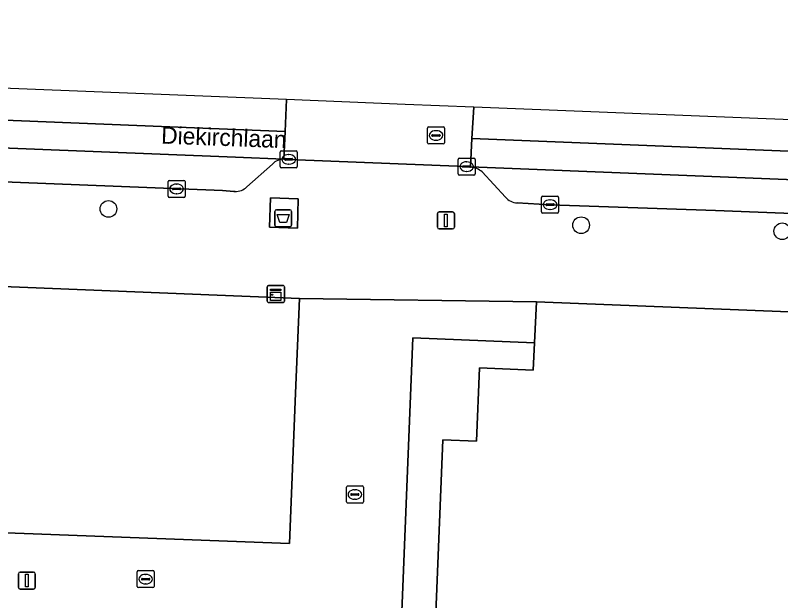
# Model space of a CAD drawing. Extents: x 160888 to 161385, y 386490 to 386908.
# Drawn here: x 161096.46 to 161141.39, y 386873.43 to 386907.8 of the extents above; entities that cross this region are included whole.
import ezdxf

# ---------------------------------------------------------------- set-up
doc = ezdxf.new("R2010")
doc.units = 0
for name, color, linetype in [('IMGEO_Afval_apart_plaats', 7, 'Continuous'), ('IMGEO_Boom', 7, 'Continuous'), ('IMGEO_Erf', 7, 'Continuous'), ('IMGEO_Kast', 7, 'Continuous'), ('IMGEO_Kolk', 7, 'Continuous'), ('IMGEO_Lichtmast', 7, 'Continuous'), ('IMGEO_Openbare_ruimte_label', 7, 'Continuous'), ('IMGEO_Pand', 7, 'Continuous'), ('IMGEO_Pand_overbouw', 7, 'Continuous'), ('IMGEO_Parkeervlak_gesloten', 7, 'Continuous'), ('IMGEO_Rijbaan_lokaal_gesloten', 7, 'Continuous'), ('IMGEO_Rioolput', 7, 'Continuous'), ('IMGEO_Voetpad_gesloten', 7, 'Continuous'), ('IMGEO_Voetpad_open', 7, 'Continuous')]:
    doc.layers.add(name, color=color, linetype=linetype)

msp = doc.modelspace()

# ---------------------------------------------------------------- linework, layer by layer
at = {"layer": 'IMGEO_Afval_apart_plaats'}
for p, q in [((161111.692, 386895.485), (161111.692, 386896.285)), ((161111.692, 386896.285), (161111.692, 386895.485)), ((161111.792, 386896.385), (161112.582, 386896.385)), ((161112.582, 386896.385), (161111.792, 386896.385)), ((161112.682, 386896.285), (161112.682, 386895.485)), ((161112.682, 386895.485), (161112.682, 386896.285)), ((161112.582, 386895.385), (161111.792, 386895.385)), ((161111.792, 386895.385), (161112.582, 386895.385))]:
    msp.add_line(p, q, dxfattribs=at)
msp.add_lwpolyline([(161111.835, 386896.099), (161112.539, 386896.099), (161112.39, 386895.629), (161111.984, 386895.629), (161111.835, 386896.099)], dxfattribs=at)
for centre, start, end in [((161111.792, 386896.285), 90, 180), ((161111.792, 386896.285), 90, 180), ((161112.582, 386896.285), 0, 90), ((161112.582, 386896.285), 360, 90), ((161111.792, 386895.485), 180, 270), ((161111.792, 386895.485), 180, 270), ((161112.582, 386895.485), 270, 0), ((161112.582, 386895.485), 270, 0)]:
    msp.add_arc(centre, 0.1, start, end, dxfattribs=at)
at = {"layer": 'IMGEO_Boom'}
for centre in [(161101.933, 386896.429), (161129.681, 386895.476), (161141.488, 386895.12)]:
    msp.add_circle(centre, 0.489, dxfattribs=at)
at = {"layer": 'IMGEO_Erf'}
msp.add_lwpolyline([(161126.941, 386888.577), (161119.79, 386888.855), (161118.549, 386857.687), (161120.551, 386857.609), (161121.042, 386870), (161120.682, 386870.014), (161120.711, 386870.76), (161121.073, 386870.746), (161121.567, 386882.869), (161123.545, 386882.788), (161123.715, 386887.092), (161126.862, 386886.972)], close=True, dxfattribs=at)
at = {"layer": 'IMGEO_Kast'}
for p, q in [((161111.258, 386891.006), (161111.258, 386891.847)), ((161111.258, 386891.847), (161111.258, 386891.006)), ((161111.333, 386891.931), (161112.174, 386891.931)), ((161112.174, 386891.931), (161111.333, 386891.931)), ((161112.258, 386891.856), (161112.258, 386891.015)), ((161112.258, 386891.015), (161112.258, 386891.856)), ((161112.183, 386890.931), (161111.342, 386890.931)), ((161111.342, 386890.931), (161112.183, 386890.931))]:
    msp.add_line(p, q, dxfattribs=at)
for points in [[(161111.453, 386891.721), (161112.053, 386891.721), (161112.053, 386891.636), (161111.453, 386891.636), (161111.453, 386891.721)], [(161111.453, 386891.546), (161112.053, 386891.546), (161112.053, 386891.057), (161111.453, 386891.057), (161111.453, 386891.546)]]:
    msp.add_lwpolyline(points, dxfattribs=at)
msp.add_circle((161111.537, 386891.395), 0.0377, dxfattribs=at)
for centre, start, end in [((161111.336, 386891.853), 92.4484, 184.2845), ((161111.336, 386891.853), 92.4484, 184.2845), ((161112.18, 386891.853), 2.4484, 94.2845), ((161112.18, 386891.853), 2.4484, 94.2845), ((161111.336, 386891.009), 182.4484, 274.2845), ((161111.336, 386891.009), 182.4484, 274.2845), ((161112.18, 386891.009), 272.4484, 4.2845), ((161112.18, 386891.009), 272.4484, 4.2845)]:
    msp.add_arc(centre, 0.0779, start, end, dxfattribs=at)
at = {"layer": 'IMGEO_Kolk'}
for p, q in [((161112.016, 386898.914), (161112.016, 386899.766)), ((161112.091, 386899.84), (161112.943, 386899.84)), ((161112.504, 386899.62), (161112.529, 386899.62)), ((161113.017, 386899.766), (161113.017, 386898.914)), ((161112.275, 386899.334), (161112.275, 386899.346)), ((161112.713, 386899.297), (161112.315, 386899.297)), ((161112.318, 386899.383), (161112.716, 386899.383)), ((161112.759, 386899.346), (161112.759, 386899.334)), ((161122.459, 386898.49), (161122.459, 386899.342)), ((161122.534, 386899.416), (161123.386, 386899.416)), ((161122.947, 386899.196), (161122.972, 386899.196)), ((161123.46, 386899.342), (161123.46, 386898.49)), ((161112.943, 386898.84), (161112.091, 386898.84)), ((161112.527, 386899.06), (161112.502, 386899.06)), ((161122.718, 386898.91), (161122.718, 386898.922)), ((161123.156, 386898.873), (161122.758, 386898.873)), ((161122.761, 386898.959), (161123.159, 386898.959)), ((161123.202, 386898.922), (161123.202, 386898.91)), ((161123.386, 386898.416), (161122.534, 386898.416)), ((161122.97, 386898.636), (161122.945, 386898.636)), ((161105.43, 386897.18), (161105.43, 386898.032)), ((161105.505, 386898.106), (161106.357, 386898.106)), ((161105.918, 386897.886), (161105.943, 386897.886)), ((161106.431, 386898.032), (161106.431, 386897.18)), ((161105.689, 386897.6), (161105.689, 386897.612)), ((161106.127, 386897.563), (161105.729, 386897.563)), ((161105.732, 386897.649), (161106.13, 386897.649)), ((161106.173, 386897.612), (161106.173, 386897.6)), ((161106.357, 386897.106), (161105.505, 386897.106)), ((161105.941, 386897.326), (161105.916, 386897.326)), ((161127.358, 386896.252), (161127.358, 386897.104)), ((161127.433, 386897.178), (161128.285, 386897.178)), ((161127.846, 386896.958), (161127.871, 386896.958)), ((161128.359, 386897.104), (161128.359, 386896.252)), ((161127.617, 386896.672), (161127.617, 386896.684)), ((161128.055, 386896.635), (161127.657, 386896.635)), ((161127.66, 386896.721), (161128.058, 386896.721)), ((161128.101, 386896.684), (161128.101, 386896.672)), ((161128.285, 386896.178), (161127.433, 386896.178)), ((161127.869, 386896.398), (161127.844, 386896.398)), ((161115.896, 386879.235), (161115.896, 386880.087)), ((161115.971, 386880.161), (161116.823, 386880.161)), ((161116.384, 386879.941), (161116.409, 386879.941)), ((161116.897, 386880.087), (161116.897, 386879.235)), ((161116.155, 386879.655), (161116.155, 386879.667)), ((161116.593, 386879.618), (161116.195, 386879.618)), ((161116.198, 386879.704), (161116.596, 386879.704)), ((161116.639, 386879.667), (161116.639, 386879.655)), ((161116.823, 386879.161), (161115.971, 386879.161)), ((161116.407, 386879.381), (161116.382, 386879.381)), ((161103.615, 386874.267), (161103.615, 386875.119)), ((161103.69, 386875.193), (161104.542, 386875.193)), ((161104.103, 386874.973), (161104.128, 386874.973)), ((161104.616, 386875.119), (161104.616, 386874.267)), ((161103.874, 386874.687), (161103.874, 386874.699)), ((161104.312, 386874.65), (161103.914, 386874.65)), ((161103.917, 386874.736), (161104.315, 386874.736)), ((161104.358, 386874.699), (161104.358, 386874.687)), ((161104.542, 386874.193), (161103.69, 386874.193)), ((161104.126, 386874.413), (161104.101, 386874.413))]:
    msp.add_line(p, q, dxfattribs=at)
for points in [[(161112.016, 386898.914), (161112.016, 386899.766)], [(161112.091, 386899.84), (161112.943, 386899.84)], [(161113.017, 386899.766), (161113.017, 386898.914)], [(161122.459, 386898.49), (161122.459, 386899.342)], [(161122.534, 386899.416), (161123.386, 386899.416)], [(161123.46, 386899.342), (161123.46, 386898.49)], [(161112.943, 386898.84), (161112.091, 386898.84)], [(161123.386, 386898.416), (161122.534, 386898.416)], [(161105.43, 386897.18), (161105.43, 386898.032)], [(161105.505, 386898.106), (161106.357, 386898.106)], [(161106.431, 386898.032), (161106.431, 386897.18)], [(161106.357, 386897.106), (161105.505, 386897.106)], [(161127.358, 386896.252), (161127.358, 386897.104)], [(161127.433, 386897.178), (161128.285, 386897.178)], [(161128.359, 386897.104), (161128.359, 386896.252)], [(161128.285, 386896.178), (161127.433, 386896.178)], [(161115.896, 386879.235), (161115.896, 386880.087)], [(161115.971, 386880.161), (161116.823, 386880.161)], [(161116.897, 386880.087), (161116.897, 386879.235)], [(161116.823, 386879.161), (161115.971, 386879.161)], [(161103.615, 386874.267), (161103.615, 386875.119)], [(161103.69, 386875.193), (161104.542, 386875.193)], [(161104.616, 386875.119), (161104.616, 386874.267)], [(161104.542, 386874.193), (161103.69, 386874.193)]]:
    msp.add_lwpolyline(points, dxfattribs=at)
for centre, radius, start, end in [((161112.093, 386899.764), 0.0765, 91.552, 178.448), ((161112.093, 386899.764), 0.0765, 91.552, 178.448), ((161112.941, 386899.764), 0.0765, 1.552, 88.448), ((161112.941, 386899.764), 0.0765, 1.552, 88.448), ((161112.315, 386899.343), 0.0403, 85.8775, 175.7526), ((161112.312, 386899.333), 0.0366, 178.938, 274.7102), ((161112.716, 386899.34), 0.043, 264.8664, 352.4533), ((161112.72, 386899.345), 0.0386, 1.7309, 96.639), ((161122.536, 386899.34), 0.0765, 91.552, 178.448), ((161122.536, 386899.34), 0.0765, 91.552, 178.448), ((161123.384, 386899.34), 0.0765, 1.552, 88.448), ((161123.384, 386899.34), 0.0765, 1.552, 88.448), ((161112.093, 386898.916), 0.0765, 181.552, 268.448), ((161112.093, 386898.916), 0.0765, 181.552, 268.448), ((161112.941, 386898.916), 0.0765, 271.552, 358.448), ((161112.941, 386898.916), 0.0765, 271.552, 358.448), ((161122.758, 386898.919), 0.0403, 85.8775, 175.7526), ((161122.755, 386898.909), 0.0366, 178.938, 274.7102), ((161123.159, 386898.916), 0.043, 264.8664, 352.4533), ((161123.163, 386898.921), 0.0386, 1.7309, 96.639), ((161122.536, 386898.492), 0.0765, 181.552, 268.448), ((161122.536, 386898.492), 0.0765, 181.552, 268.448), ((161123.384, 386898.492), 0.0765, 271.552, 358.448), ((161123.384, 386898.492), 0.0765, 271.552, 358.448), ((161105.507, 386898.03), 0.0765, 91.552, 178.448), ((161105.507, 386898.03), 0.0765, 91.552, 178.448), ((161106.355, 386898.03), 0.0765, 1.552, 88.448), ((161106.355, 386898.03), 0.0765, 1.552, 88.448), ((161105.729, 386897.609), 0.0403, 85.8775, 175.7526), ((161105.726, 386897.599), 0.0366, 178.938, 274.7102), ((161106.13, 386897.606), 0.043, 264.8664, 352.4533), ((161106.134, 386897.611), 0.0386, 1.7309, 96.639), ((161105.507, 386897.182), 0.0765, 181.552, 268.448), ((161105.507, 386897.182), 0.0765, 181.552, 268.448), ((161106.355, 386897.182), 0.0765, 271.552, 358.448), ((161106.355, 386897.182), 0.0765, 271.552, 358.448), ((161127.435, 386897.102), 0.0765, 91.552, 178.448), ((161127.435, 386897.102), 0.0765, 91.552, 178.448), ((161128.283, 386897.102), 0.0765, 1.552, 88.448), ((161128.283, 386897.102), 0.0765, 1.552, 88.448), ((161127.657, 386896.681), 0.0403, 85.8775, 175.7526), ((161127.654, 386896.671), 0.0366, 178.938, 274.7102), ((161128.058, 386896.678), 0.043, 264.8664, 352.4533), ((161128.062, 386896.683), 0.0386, 1.7309, 96.639), ((161127.435, 386896.254), 0.0765, 181.552, 268.448), ((161127.435, 386896.254), 0.0765, 181.552, 268.448), ((161128.283, 386896.254), 0.0765, 271.552, 358.448), ((161128.283, 386896.254), 0.0765, 271.552, 358.448), ((161115.973, 386880.085), 0.0765, 91.552, 178.448), ((161115.973, 386880.085), 0.0765, 91.552, 178.448), ((161116.821, 386880.085), 0.0765, 1.552, 88.448), ((161116.821, 386880.085), 0.0765, 1.552, 88.448), ((161116.195, 386879.664), 0.0403, 85.8775, 175.7526), ((161116.192, 386879.654), 0.0366, 178.938, 274.7102), ((161116.596, 386879.661), 0.043, 264.8664, 352.4533), ((161116.6, 386879.666), 0.0386, 1.7309, 96.639), ((161115.973, 386879.237), 0.0765, 181.552, 268.448), ((161115.973, 386879.237), 0.0765, 181.552, 268.448), ((161116.821, 386879.237), 0.0765, 271.552, 358.448), ((161116.821, 386879.237), 0.0765, 271.552, 358.448), ((161103.692, 386875.117), 0.0765, 91.552, 178.448), ((161103.692, 386875.117), 0.0765, 91.552, 178.448), ((161104.54, 386875.117), 0.0765, 1.552, 88.448), ((161104.54, 386875.117), 0.0765, 1.552, 88.448), ((161103.914, 386874.696), 0.0403, 85.8775, 175.7526), ((161103.911, 386874.686), 0.0366, 178.938, 274.7102), ((161104.315, 386874.693), 0.043, 264.8664, 352.4533), ((161104.319, 386874.698), 0.0386, 1.7309, 96.639), ((161103.692, 386874.269), 0.0765, 181.552, 268.448), ((161103.692, 386874.269), 0.0765, 181.552, 268.448), ((161104.54, 386874.269), 0.0765, 271.552, 358.448), ((161104.54, 386874.269), 0.0765, 271.552, 358.448)]:
    msp.add_arc(centre, radius, start, end, dxfattribs=at)
for centre, major_axis, ratio, start_param, end_param in [((161112.503, 386899.34), (-0.387, 0.002), 0.722429, 4.712389, 7.853982), ((161112.528, 386899.34), (-0.39, 0.002), 0.717154, 1.570796, 4.712389), ((161122.946, 386898.916), (-0.387, 0.002), 0.722429, 4.712389, 7.853982), ((161122.971, 386898.916), (-0.39, 0.002), 0.717154, 1.570796, 4.712389), ((161105.917, 386897.606), (-0.387, 0.002), 0.722429, 4.712389, 7.853982), ((161105.942, 386897.606), (-0.39, 0.002), 0.717154, 1.570796, 4.712389), ((161127.845, 386896.678), (-0.387, 0.002), 0.722429, 4.712389, 7.853982), ((161127.87, 386896.678), (-0.39, 0.002), 0.717154, 1.570796, 4.712389), ((161116.383, 386879.661), (-0.387, 0.002), 0.722429, 4.712389, 7.853982), ((161116.408, 386879.661), (-0.39, 0.002), 0.717154, 1.570796, 4.712389), ((161104.102, 386874.693), (-0.387, 0.002), 0.722429, 4.712389, 7.853982), ((161104.127, 386874.693), (-0.39, 0.002), 0.717154, 1.570796, 4.712389)]:
    msp.add_ellipse(centre, major_axis=major_axis, ratio=ratio, start_param=start_param, end_param=end_param, dxfattribs=at)
at = {"layer": 'IMGEO_Lichtmast'}
for p, q in [((161121.247, 386895.357), (161121.247, 386896.157)), ((161121.247, 386896.157), (161121.247, 386895.357)), ((161121.347, 386896.257), (161122.137, 386896.257)), ((161122.137, 386896.257), (161121.347, 386896.257)), ((161122.237, 386896.157), (161122.237, 386895.357)), ((161122.237, 386895.357), (161122.237, 386896.157)), ((161122.137, 386895.257), (161121.347, 386895.257)), ((161121.347, 386895.257), (161122.137, 386895.257)), ((161096.648, 386874.209), (161096.648, 386875.009)), ((161096.648, 386875.009), (161096.648, 386874.209)), ((161096.748, 386875.109), (161097.538, 386875.109)), ((161097.538, 386875.109), (161096.748, 386875.109)), ((161097.638, 386875.009), (161097.638, 386874.209)), ((161097.638, 386874.209), (161097.638, 386875.009)), ((161097.538, 386874.109), (161096.748, 386874.109)), ((161096.748, 386874.109), (161097.538, 386874.109))]:
    msp.add_line(p, q, dxfattribs=at)
for points in [[(161121.667, 386896.132), (161121.817, 386896.132), (161121.817, 386895.382), (161121.667, 386895.382), (161121.667, 386896.132)], [(161097.068, 386874.984), (161097.218, 386874.984), (161097.218, 386874.234), (161097.068, 386874.234), (161097.068, 386874.984)]]:
    msp.add_lwpolyline(points, dxfattribs=at)
for centre, start, end in [((161121.347, 386896.157), 90, 180), ((161121.347, 386896.157), 90, 180), ((161122.137, 386896.157), 0, 90), ((161122.137, 386896.157), 360, 90), ((161121.347, 386895.357), 180, 270), ((161121.347, 386895.357), 180, 270), ((161122.137, 386895.357), 270, 0), ((161122.137, 386895.357), 270, 0), ((161096.748, 386875.009), 90, 180), ((161096.748, 386875.009), 90, 180), ((161097.538, 386875.009), 0, 90), ((161097.538, 386875.009), 360, 90), ((161096.748, 386874.209), 180, 270), ((161096.748, 386874.209), 180, 270), ((161097.538, 386874.209), 270, 0), ((161097.538, 386874.209), 270, 0)]:
    msp.add_arc(centre, 0.1, start, end, dxfattribs=at)
at = {"layer": 'IMGEO_Pand'}
for points in [[(161113.143, 386891.17), (161097.194, 386891.813), (161080.645, 386892.481), (161055.667, 386893.489), (161046.293, 386893.867), (161046.299, 386893.997), (161046.043, 386894.008), (161045.711, 386885.882), (161045.442, 386879.308), (161047.716, 386879.222), (161049.049, 386879.172), (161064.569, 386878.588), (161069.116, 386878.417), (161073.594, 386878.249), (161112.563, 386876.783), (161112.919, 386885.615)], [(161120.067, 386845.369), (161194.586, 386842.427), (161196.377, 386887.78), (161196.381, 386887.886), (161196.395, 386888.23), (161188.186, 386888.554), (161178.427, 386888.94), (161127.058, 386890.969), (161126.941, 386888.577), (161126.862, 386886.972), (161123.715, 386887.092), (161123.545, 386882.788), (161121.567, 386882.869), (161121.073, 386870.746), (161120.711, 386870.76), (161120.682, 386870.014), (161121.042, 386870), (161120.551, 386857.609)]]:
    msp.add_lwpolyline(points, close=True, dxfattribs=at)
at = {"layer": 'IMGEO_Pand_overbouw'}
msp.add_lwpolyline([(161120.551, 386857.609), (161121.042, 386870), (161120.682, 386870.014), (161120.711, 386870.76), (161121.073, 386870.746), (161121.567, 386882.869), (161123.545, 386882.788), (161123.715, 386887.092), (161126.862, 386886.972), (161126.941, 386888.577), (161119.79, 386888.855), (161118.549, 386857.687), (161118.629, 386857.684)], close=True, dxfattribs=at)
at = {"layer": 'IMGEO_Parkeervlak_gesloten'}
for points in [[(161112.234, 386899.353), (161109.397, 386899.476), (161073.486, 386900.908), (161073.403, 386898.925), (161074.03, 386898.891), (161108.628, 386897.506), (161109.298, 386897.46), (161109.361, 386897.456)], [(161110.048, 386897.723), (161111.567, 386899.063)], [(161155.904, 386897.594), (161123.188, 386898.901), (161122.96, 386898.916), (161122.897, 386898.919), (161123.175, 386898.874)], [(161123.877, 386898.605), (161125.249, 386897.126)], [(161125.921, 386896.787), (161127.859, 386896.678), (161137.577, 386896.347), (161155.616, 386895.637), (161155.851, 386895.628), (161155.904, 386897.594)]]:
    msp.add_lwpolyline(points, dxfattribs=at)
for centre, radius, start, end in [((161112.22, 386898.474), 0.879, 89.0729, 137.9243), ((161123.116, 386897.668), 1.207, 50.89, 87.1773), ((161109.409, 386898.35), 0.896, 266.9377, 315.5391), ((161125.945, 386897.669), 0.883, 217.9927, 268.4686)]:
    msp.add_arc(centre, radius, start, end, dxfattribs=at)
at = {"layer": 'IMGEO_Rijbaan_lokaal_gesloten'}
for points in [[(161112.38, 386902.848), (160988.148, 386907.8), (160987.595, 386907.148)], [(160986.431, 386905.776), (160986.431, 386905.776), (160987.414, 386904.997), (160988.842, 386904.061), (160989.598, 386903.645), (160992.187, 386902.648), (160994.092, 386902.091), (160996.449, 386901.746), (160999.189, 386901.61), (161000, 386901.579), (161012.233, 386901.108), (161035.324, 386900.473), (161035.479, 386900.468), (161040.028, 386900.281), (161040.12, 386902.25), (161064.059, 386901.284), (161073.486, 386900.908), (161109.397, 386899.476), (161112.234, 386899.353), (161112.299, 386900.982), (161040.205, 386903.901), (161035.665, 386902.345), (160996.157, 386903.935)], [(160996.157, 386903.935), (161035.665, 386902.345), (161040.205, 386903.901), (161112.299, 386900.982), (161112.38, 386902.848)], [(161291.165, 386895.721), (161123.374, 386902.409), (161123.263, 386900.56), (161248.069, 386895.57), (161278.544, 386894.358), (161279.11, 386894.349), (161286.088, 386894.243)]]:
    msp.add_lwpolyline(points, dxfattribs=at)
for points in [[(161123.374, 386902.409), (161119.345, 386902.57), (161112.38, 386902.848), (161112.299, 386900.982), (161112.234, 386899.353), (161112.26, 386899.352), (161112.517, 386899.34), (161122.897, 386898.919), (161122.96, 386898.916), (161123.188, 386898.901), (161123.263, 386900.56)], [(161279.11, 386894.349), (161278.544, 386894.358), (161248.069, 386895.57), (161123.263, 386900.56), (161123.188, 386898.901), (161155.904, 386897.594), (161176.778, 386896.8), (161194.86, 386896.072), (161209.056, 386895.484), (161221.008, 386894.938), (161241.882, 386894.123), (161247.927, 386893.867), (161258.887, 386893.342), (161276.971, 386892.717), (161277.593, 386892.717), (161277.832, 386892.705), (161279.059, 386892.659)]]:
    msp.add_lwpolyline(points, close=True, dxfattribs=at)
at = {"layer": 'IMGEO_Rioolput'}
for p, q in [((161120.662, 386900.32), (161120.662, 386901.172)), ((161120.737, 386901.246), (161121.589, 386901.246)), ((161121.15, 386901.026), (161121.175, 386901.026)), ((161121.663, 386901.172), (161121.663, 386900.32)), ((161120.921, 386900.74), (161120.921, 386900.752)), ((161121.359, 386900.703), (161120.961, 386900.703)), ((161120.964, 386900.789), (161121.362, 386900.789)), ((161121.405, 386900.752), (161121.405, 386900.74)), ((161121.589, 386900.246), (161120.737, 386900.246)), ((161121.173, 386900.466), (161121.148, 386900.466))]:
    msp.add_line(p, q, dxfattribs=at)
for points in [[(161120.662, 386900.32), (161120.662, 386901.172)], [(161120.737, 386901.246), (161121.589, 386901.246)], [(161121.663, 386901.172), (161121.663, 386900.32)], [(161121.589, 386900.246), (161120.737, 386900.246)]]:
    msp.add_lwpolyline(points, dxfattribs=at)
for centre, radius, start, end in [((161120.739, 386901.17), 0.0765, 91.552, 178.448), ((161120.739, 386901.17), 0.0765, 91.552, 178.448), ((161121.587, 386901.17), 0.0765, 1.552, 88.448), ((161121.587, 386901.17), 0.0765, 1.552, 88.448), ((161120.961, 386900.749), 0.0403, 85.8775, 175.7526), ((161120.958, 386900.739), 0.0366, 178.938, 274.7102), ((161121.362, 386900.746), 0.043, 264.8664, 352.4533), ((161121.366, 386900.751), 0.0386, 1.7309, 96.639), ((161120.739, 386900.322), 0.0765, 181.552, 268.448), ((161120.739, 386900.322), 0.0765, 181.552, 268.448), ((161121.587, 386900.322), 0.0765, 271.552, 358.448), ((161121.587, 386900.322), 0.0765, 271.552, 358.448)]:
    msp.add_arc(centre, radius, start, end, dxfattribs=at)
for centre, major_axis, ratio, start_param, end_param in [((161121.149, 386900.746), (-0.387, 0.002), 0.722429, 4.712389, 7.853982), ((161121.174, 386900.746), (-0.39, 0.002), 0.717154, 1.570796, 4.712389)]:
    msp.add_ellipse(centre, major_axis=major_axis, ratio=ratio, start_param=start_param, end_param=end_param, dxfattribs=at)
at = {"layer": 'IMGEO_Voetpad_gesloten'}
msp.add_lwpolyline([(161111.443, 386897.079), (161111.388, 386895.362), (161113.02, 386895.309), (161113.076, 386897.03)], close=True, dxfattribs=at)
at = {"layer": 'IMGEO_Voetpad_open'}
for points in [[(160986.001, 386902.936), (160981.133, 386897.248), (160982.853, 386895.847), (160984.295, 386894.643), (160993.236, 386896.016), (161004.65, 386895.537), (161029.981, 386894.476), (161035.955, 386894.217), (161041.701, 386893.968), (161046.043, 386894.008), (161046.299, 386893.997), (161046.293, 386893.867), (161055.667, 386893.489), (161080.645, 386892.481), (161097.194, 386891.813), (161113.143, 386891.17), (161127.058, 386890.969), (161178.427, 386888.94)], [(161109.361, 386897.456), (161109.298, 386897.46), (161108.628, 386897.506), (161074.03, 386898.891), (161073.403, 386898.925), (161071.838, 386899.01), (161071.724, 386897.893), (161068.662, 386898.016), (161065.732, 386898.135), (161065.827, 386899.252), (161064.015, 386899.299), (161063.696, 386899.307), (161040.028, 386900.281), (161035.479, 386900.468), (161035.324, 386900.473)], [(161123.175, 386898.874), (161122.897, 386898.919), (161112.517, 386899.34), (161112.26, 386899.352), (161112.234, 386899.353)], [(161111.567, 386899.063), (161110.048, 386897.723)], [(161125.249, 386897.126), (161123.877, 386898.605)], [(161155.616, 386895.637), (161137.577, 386896.347), (161127.859, 386896.678), (161125.921, 386896.787)], [(161119.79, 386888.855), (161126.941, 386888.577), (161127.058, 386890.969), (161113.143, 386891.17), (161112.919, 386885.615), (161112.563, 386876.783), (161073.594, 386878.249), (161073.583, 386877.375), (161070.12, 386877.508), (161064.537, 386877.72), (161064.569, 386878.588), (161049.049, 386879.172), (161049.023, 386878.446), (161048.048, 386878.482), (161045.473, 386878.577)], [(160988.113, 386879.42), (160988.085, 386877.583), (160973.52, 386878.149), (160973.222, 386870.514), (160982.977, 386870.114), (160983.988, 386870.07), (160998.471, 386869.439), (161000, 386869.372), (161002.18, 386869.277), (161017.574, 386868.605), (161022.345, 386868.321), (161040.517, 386867.696), (161042.835, 386870.038), (161086.005, 386868.407), (161091.101, 386868.215), (161100.979, 386872.509), (161105.986, 386872.318), (161110.434, 386872.136), (161115.457, 386871.94), (161115.257, 386866.814), (161118.549, 386857.687), (161119.79, 386888.855)]]:
    msp.add_lwpolyline(points, dxfattribs=at)
msp.add_lwpolyline([(161111.443, 386897.079), (161113.076, 386897.03), (161113.02, 386895.309), (161111.388, 386895.362)], close=True, dxfattribs=at)
for centre, radius, start, end in [((161112.22, 386898.474), 0.879, 89.0729, 137.9243), ((161123.116, 386897.668), 1.207, 50.89, 87.1773), ((161109.409, 386898.35), 0.896, 266.9377, 315.5391), ((161125.945, 386897.669), 0.883, 217.9927, 268.4686)]:
    msp.add_arc(centre, radius, start, end, dxfattribs=at)

# ---------------------------------------------------------------- texts
at = {"layer": 'IMGEO_Openbare_ruimte_label'}
msp.add_text('Diekirchlaan', height=1, rotation=357.8789, dxfattribs=at).set_placement((161105.012, 386900.269))

doc.saveas('drawing.dxf')
